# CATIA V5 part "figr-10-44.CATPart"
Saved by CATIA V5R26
Part number: Part1
Bounding box of the stored display mesh (mm): x -20 to 20, y -0.339 to 152.641, z -44.55 to 10.195
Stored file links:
  D:\_Deepak\CATIA\CATIA V5-6R2016_Deepak\Resources\Part files\Partfiles\c10_catia_v5_6r2016_prt\figr-10-44.CATPart
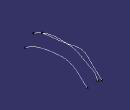
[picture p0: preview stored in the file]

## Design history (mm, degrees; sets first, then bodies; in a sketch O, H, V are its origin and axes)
Set1
  Plane1: type Offset, RefPlane yz-plane, Offset 20, reversed
  Sketch1 on yz-plane, origin (0, 0, 0), H (0, 1, 0), V (0, 0, 1)
    spline S1 through (-0.3393, -8.9363) (20.4957, 1.6782) (43.9804, 9.0119) (85.9797, 8.8277) (110.0875, 1.9736) (113.4186, 0.0053) (148.283, -20.6228) (152.6411, -30.7916)
  Sketch2 on Plane1, origin (-20, 0, 0), H (0, 1, 0), V (0, 0, 1)
    spline S1 through (0, -18.2863) (39.7074, -13.5111) (76.5446, -6.6894) (104.5136, -9.077) (112.3585, -15.8987) (129.7538, -32.6118) (143.3972, -44.5498)
  Plane2: type Offset, RefPlane yz-plane, Offset 20
  Sketch3 on Plane2, origin (20, 0, 0), H (0, 1, 0), V (0, 0, 1)
    spline S1 through (0, -29.0463) (25.3574, -14.3797) (67.652, -5.1704) (115.4039, -10.2866) (140.3031, -31.4339) (148.4891, -38.2556)
Body1 (main body)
